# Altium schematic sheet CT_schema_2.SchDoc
size 398 x 262 mm
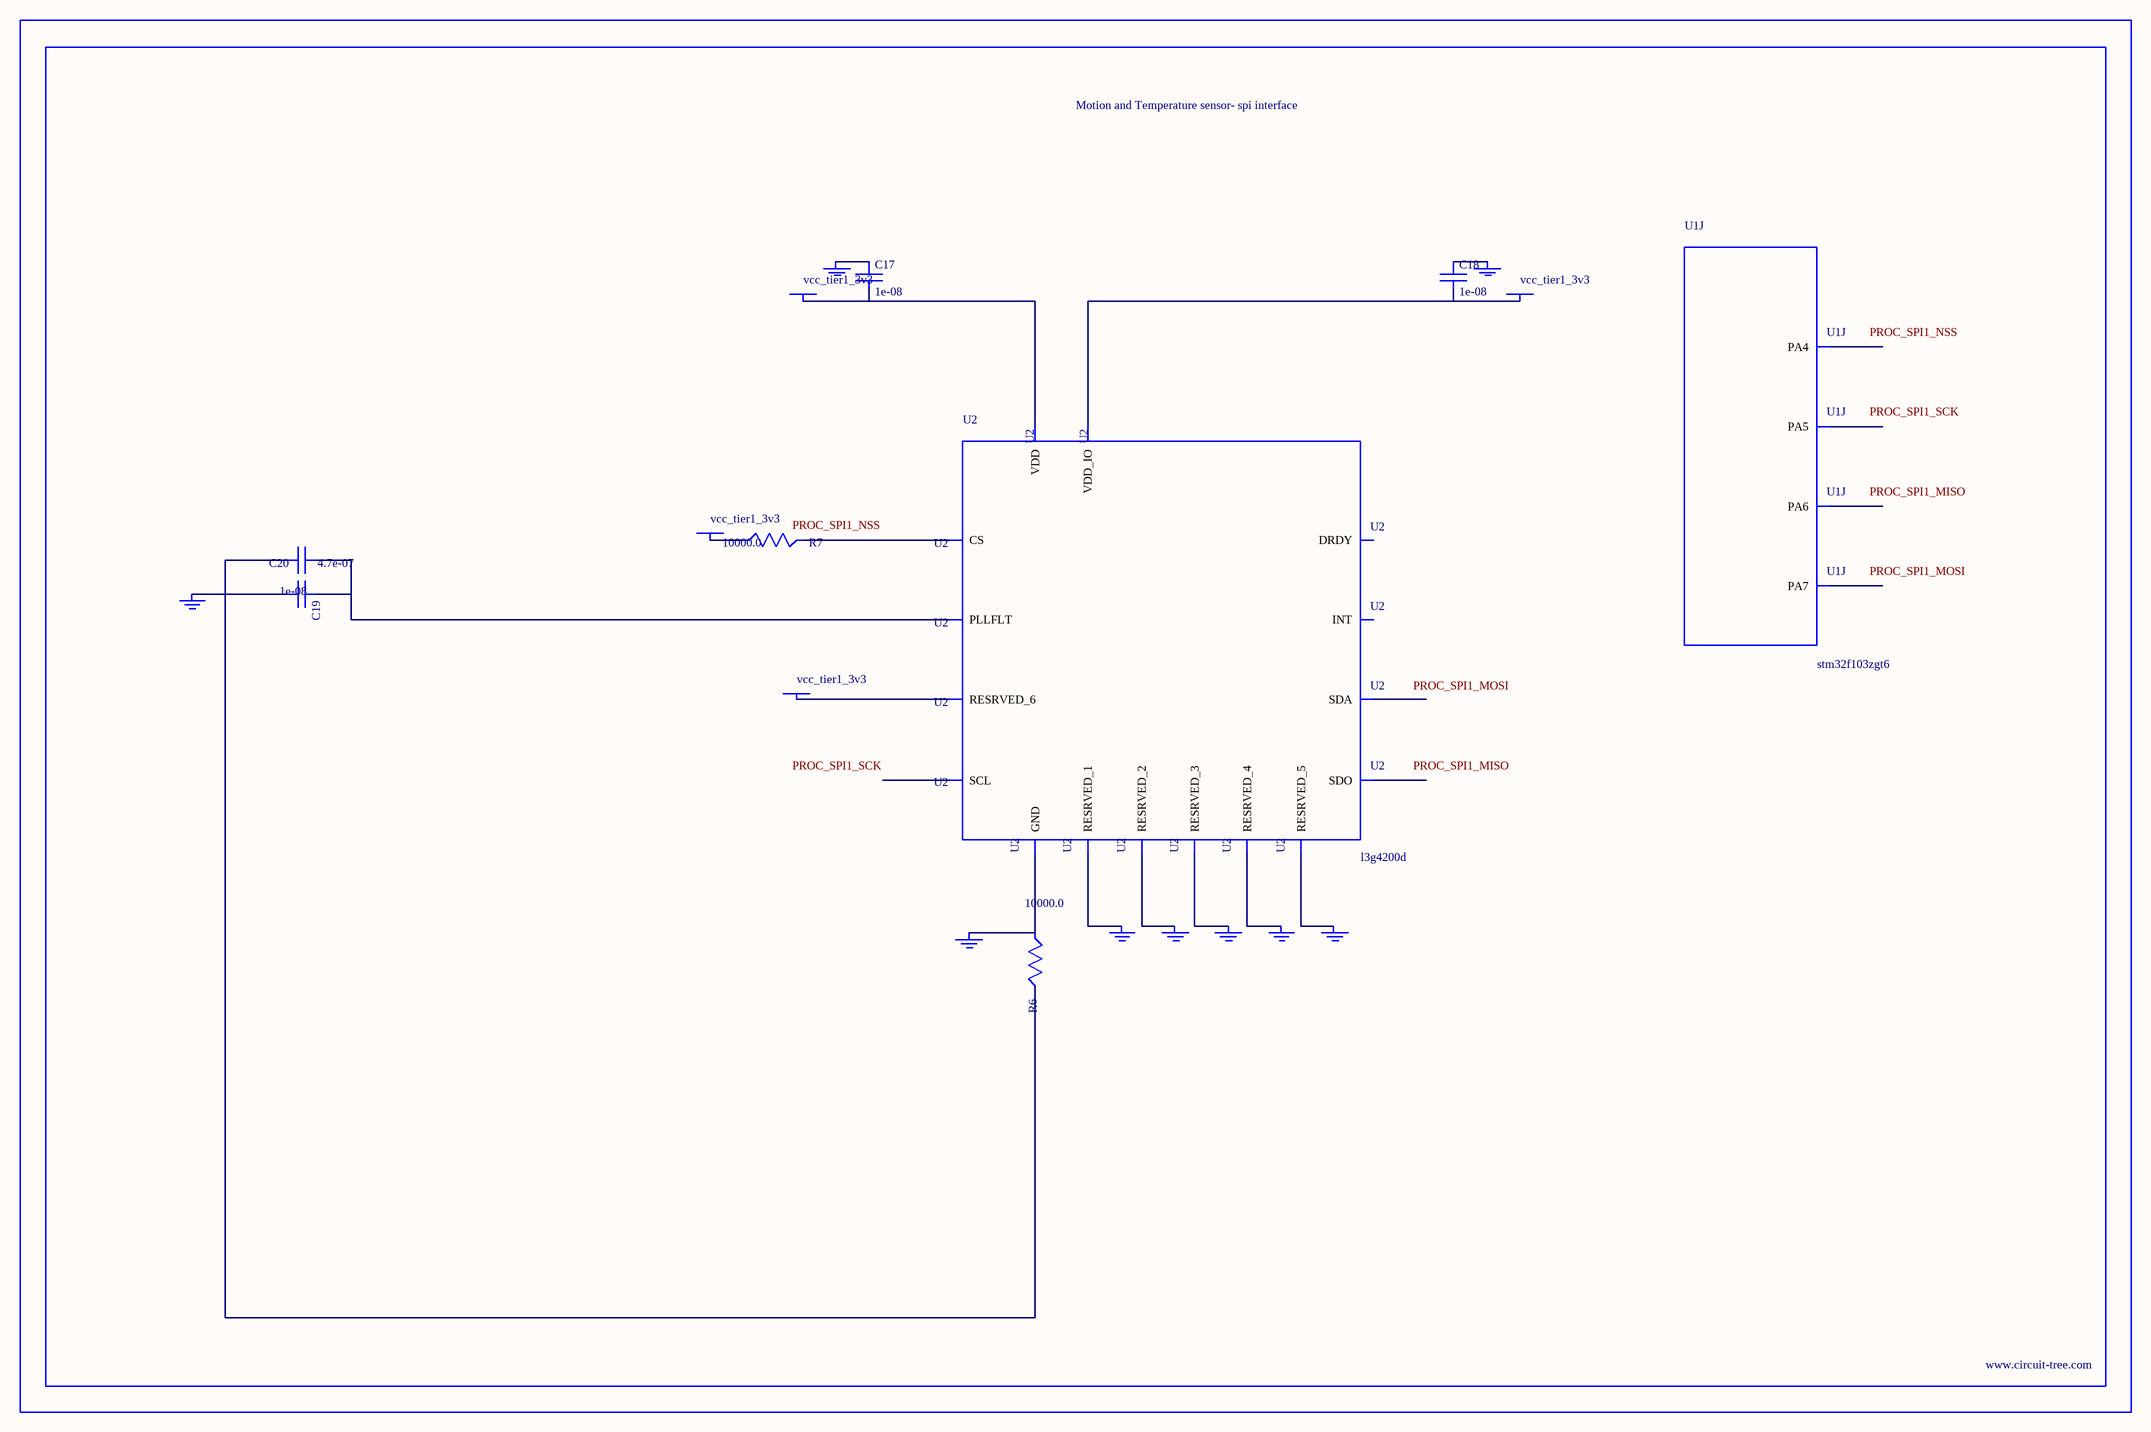
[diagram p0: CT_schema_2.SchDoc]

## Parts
BORDER1  (no value)
C17  1e-08  [C0402]
C18  1e-08  [C0402]
C19  1e-08  [C0402]
C20  4.7e-07  [C0603]
GND_INSTANCE_1_0  (no value)
GND_INSTANCE_1_1  (no value)
GND_INSTANCE_1_2  (no value)
GND_INSTANCE_1_3  (no value)
GND_INSTANCE_1_4  (no value)
GND_INSTANCE_1_5  (no value)
GND_INSTANCE_1_6  (no value)
GND_INSTANCE_1_7  (no value)
GND_INSTANCE_1_8  (no value)
POWER_INSTANCE_1_0  vcc_tier1_3v3
POWER_INSTANCE_1_1  vcc_tier1_3v3
POWER_INSTANCE_1_2  vcc_tier1_3v3
POWER_INSTANCE_1_3  vcc_tier1_3v3
R6  10000.0  [R0603]
R7  10000.0  [R0603]
U1  stm32f103zgt6  [LQFP144]  (part J of 12)
U2  l3g4200d  [LGA-16]

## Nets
NetC17_1: C17.1 GND_INSTANCE_1_8.0(GND)
NetC17_2: C17.2 POWER_INSTANCE_1_3.0(PWR) U2.16(VDD)
NetC18_1: C18.1 GND_INSTANCE_1_0.0(GND)
NetC18_2: C18.2 POWER_INSTANCE_1_0.0(PWR) U2.1(VDD_IO)
NetC19_1: C19.1 C20.1 U2.14(PLLFLT)
NetC19_2: C19.2 C20.2 GND_INSTANCE_1_7.0(GND) R6.2
NetGND_INSTANCE_1_1_0: GND_INSTANCE_1_1.0(GND) U2.8(RESRVED_1)
NetGND_INSTANCE_1_2_0: GND_INSTANCE_1_2.0(GND) U2.9(RESRVED_2)
NetGND_INSTANCE_1_3_0: GND_INSTANCE_1_3.0(GND) U2.10(RESRVED_3)
NetGND_INSTANCE_1_4_0: GND_INSTANCE_1_4.0(GND) U2.11(RESRVED_4)
NetGND_INSTANCE_1_5_0: GND_INSTANCE_1_5.0(GND) U2.12(RESRVED_5)
NetGND_INSTANCE_1_6_0: GND_INSTANCE_1_6.0(GND) R6.1 U2.13(GND)
NetPOWER_INSTANCE_1_1_0: POWER_INSTANCE_1_1.0(PWR) R7.1
NetPOWER_INSTANCE_1_2_0: POWER_INSTANCE_1_2.0(PWR) U2.15(RESRVED_6)
NetR7_2: R7.2 U2.5(CS)

Not connected (* = marked no-connect by the designer): U1 40(PA4) 41(PA5) 42(PA6) 43(PA7); U2 2(SCL) 3(SDA) 4(SDO) 6(DRDY) 7(INT)

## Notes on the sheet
- Labels drawn without touching a wire or pin: PROC_SPI1_MISO, PROC_SPI1_MOSI, PROC_SPI1_NSS, PROC_SPI1_SCK

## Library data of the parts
BORDER1 = BORDER_PAGE1
C17-C19 = C0402C103K3RAC
C20 = C0603C474K3RAC
GND_INSTANCE_1_0-GND_INSTANCE_1_8 = GND
POWER_INSTANCE_1_0-POWER_INSTANCE_1_3 = PWR
R6 R7 = RC0603JR-0710KL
